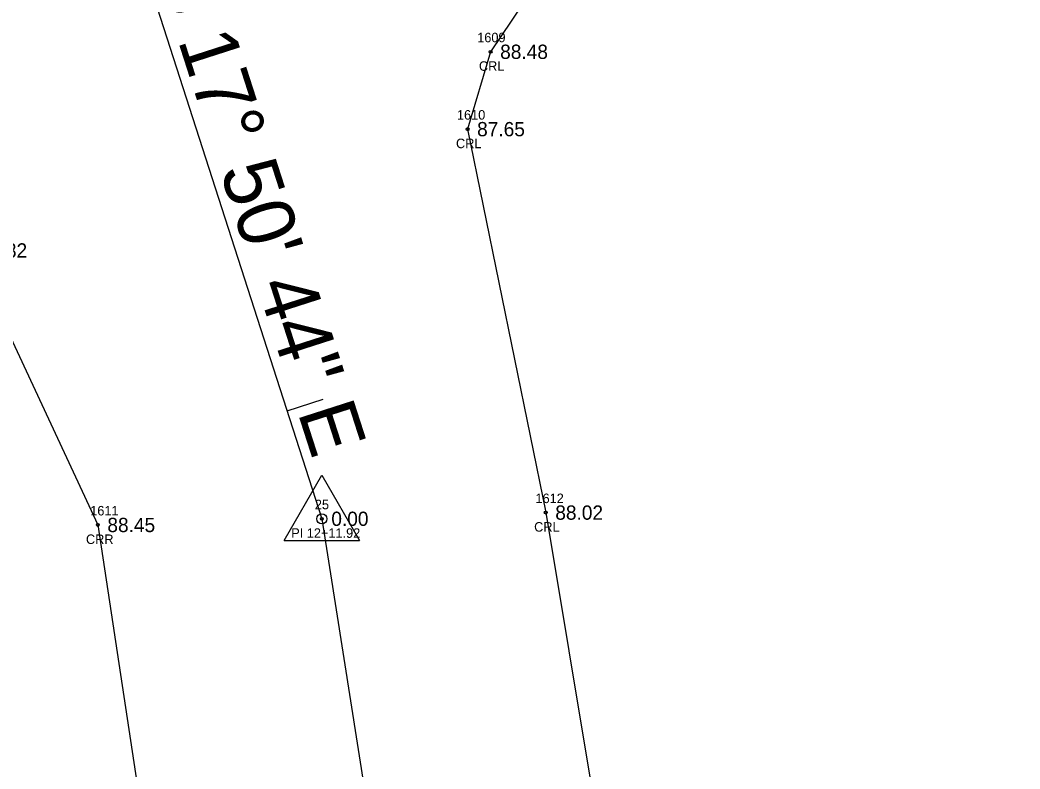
# Model space of a CAD drawing. Extents: x 2529517 to 2532038, y 935000 to 936944.
# Drawn here: x 2531126.5 to 2531231.5, y 935866 to 935944.7 of the extents above; entities that cross this region are included whole.
import ezdxf

# ---------------------------------------------------------------- set-up
doc = ezdxf.new("R2010")
doc.units = 0
for name, color, linetype in [('Default', 7, 'Continuous'), ('RD_EX_H2O', 7, 'Continuous'), ('RD_EX_H2O_txCode', 7, 'Continuous'), ('RD_EX_TX_H2O_ELEV', 7, 'Continuous'), ('RD_HC_Cl', 7, 'Continuous'), ('RD_HC_Data', 7, 'Continuous'), ('RD_HC_Data_Tic', 7, 'Continuous'), ('RD_HC_Survey_ELEV', 7, 'Continuous'), ('RD_HC_txCode', 7, 'Continuous'), ('RD_SMD_Locator', 7, 'Continuous')]:
    doc.layers.add(name, color=color, linetype=linetype)

msp = doc.modelspace()

# ---------------------------------------------------------------- linework, layer by layer
at = {"layer": 'Default'}
for p, q in [((2531138.41, 935953.66), (2531158.18, 935892.25)), ((2531158.18, 935892.25), (2531208.86, 935570.87))]:
    msp.add_line(p, q, dxfattribs=at)
at = {"layer": 'RD_EX_H2O'}
for points in [[(2531169.61, 936003.09), (2531168.21, 936006.21), (2531167.04, 936004.54), (2531167.21, 936003.45), (2531176, 935975.44), (2531176.84, 935974.76), (2531177.07, 935973.85), (2531179, 935967.11), (2531180.39, 935948.02), (2531175.92, 935941.33), (2531173.5, 935933.2), (2531181.71, 935892.9), (2531201.16, 935775.97), (2531215.24, 935672.42), (2531231.54, 935569.22), (2531229.65, 935447.9)], [(2531078.88, 935952.28), (2531078.96, 935951.18), (2531094.18, 935926.97), (2531103.29, 935929.49), (2531106.67, 935929.67), (2531109.75, 935927.85), (2531109.94, 935928.67), (2531111.53, 935928.19), (2531109.98, 935924.15), (2531114.47, 935921.71), (2531121.2, 935920.45), (2531134.65, 935891.6), (2531155.43, 935754.46), (2531173.73, 935652.91), (2531186.19, 935572.51), (2531201.43, 935446.7)]]:
    msp.add_lwpolyline(points, dxfattribs=at)
at = {"layer": 'RD_HC_Cl'}
for p, q in [((2531138.41, 935953.66), (2531158.18, 935892.25)), ((2531158.18, 935892.25), (2531208.86, 935570.87))]:
    msp.add_line(p, q, dxfattribs=at)
at = {"layer": 'RD_HC_Data'}
for p, q in [((2531154.21, 935889.96), (2531158.18, 935896.84)), ((2531158.18, 935896.84), (2531162.15, 935889.96)), ((2531154.21, 935889.96), (2531162.15, 935889.96))]:
    msp.add_line(p, q, dxfattribs=at)
msp.add_circle((2531158.18, 935892.25), 0.529, dxfattribs=at)
at = {"layer": 'RD_HC_Data_Tic'}
msp.add_line((2531154.53, 935903.59), (2531158.34, 935904.82), dxfattribs=at)
at = {"layer": 'RD_SMD_Locator'}
for centre in [(2531175.92, 935941.33), (2531173.5, 935933.2), (2531181.71, 935892.9), (2531134.65, 935891.6), (2531158.18, 935892.25)]:
    msp.add_circle(centre, 0.15, dxfattribs=at)

# ---------------------------------------------------------------- texts
at = {"layer": 'RD_EX_H2O_txCode'}
for s, p in [('1609', (2531174.51, 935942.33)), ('CRL', (2531174.69, 935939.33)), ('1610', (2531172.38, 935934.2)), ('CRL', (2531172.28, 935931.2)), ('1612', (2531180.63, 935893.9)), ('1611', (2531133.85, 935892.6)), ('CRL', (2531180.49, 935890.9)), ('CRR', (2531133.4, 935889.6))]:
    msp.add_text(s, height=1, dxfattribs=at).set_placement(p)
at = {"layer": 'RD_EX_TX_H2O_ELEV'}
for s, p in [('88.48', (2531176.92, 935940.58)), ('87.65', (2531174.5, 935932.45)), ('88.82', (2531122.2, 935919.7)), ('88.02', (2531182.71, 935892.15)), ('88.45', (2531135.65, 935890.85))]:
    msp.add_text(s, height=1.5, dxfattribs=at).set_placement(p)
at = {"layer": 'RD_HC_Data'}
msp.add_text('S 17%%d 50\' 44" E', height=6, rotation=287.8455, dxfattribs=at).set_placement((2531140.71, 935949.77))
at = {"layer": 'RD_HC_Survey_ELEV'}
msp.add_text('0.00', height=1.5, dxfattribs=at).set_placement((2531159.18, 935891.5))
at = {"layer": 'RD_HC_txCode'}
for s, p in [('25', (2531157.45, 935893.25)), ('PI 12+11.92', (2531154.97, 935890.25))]:
    msp.add_text(s, height=1, dxfattribs=at).set_placement(p)

doc.saveas('drawing.dxf')
